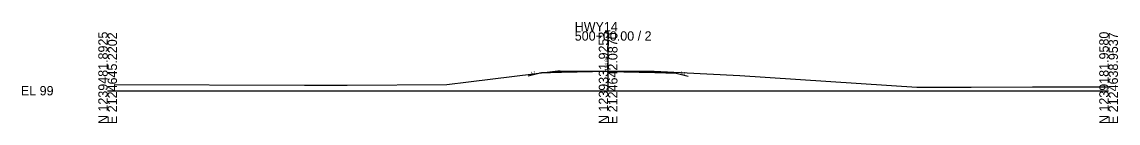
# Model space of a CAD drawing. Extents: x -26 to 303, y -10 to 11521.
# Drawn here: x -25.7 to 302.8, y 11490.3 to 11520.6 of the extents above; entities that cross this region are included whole.
import ezdxf

# ---------------------------------------------------------------- set-up
doc = ezdxf.new("R2010")
doc.units = 0
for name, color, linetype in [('XS_CELL', 7, 'Continuous'), ('XS_P_FINISHED_GRADE', 7, 'Continuous'), ('XS_P_SUBGRADE_GRANULAR', 7, 'Continuous'), ('XS_P_SUBGRADE_LEVELING', 7, 'Continuous'), ('XS_P_TX_FS_BS', 7, 'Continuous'), ('XS_X_GROUND', 7, 'Continuous'), ('XS_X_GROUND_TX', 7, 'Continuous')]:
    doc.layers.add(name, color=color, linetype=linetype)

msp = doc.modelspace()

# ---------------------------------------------------------------- linework, layer by layer
at = {"layer": 'XS_CELL'}
for p, q in [((150, 11500), (150, 11517.8)), ((0, 11500), (150, 11500)), ((150, 11500), (300, 11500))]:
    msp.add_line(p, q, dxfattribs=at)
at = {"layer": 'XS_P_FINISHED_GRADE'}
for p, q in [((130, 11505.38), (126, 11504.38)), ((136, 11505.62), (130, 11505.38)), ((150, 11505.9), (136, 11505.62)), ((150, 11505.9), (164, 11505.62)), ((164, 11505.62), (170, 11505.38)), ((170, 11505.38), (174, 11504.38))]:
    msp.add_line(p, q, dxfattribs=at)
at = {"layer": 'XS_P_SUBGRADE_GRANULAR'}
for p, q in [((136, 11505.5), (129.4, 11505.24)), ((164, 11505.5), (170.6, 11505.24))]:
    msp.add_line(p, q, dxfattribs=at)
at = {"layer": 'XS_P_SUBGRADE_LEVELING'}
for p, q in [((150, 11505.78), (136, 11505.5)), ((136, 11505.5), (136, 11505.62)), ((150, 11505.78), (164, 11505.5)), ((164, 11505.5), (164, 11505.62))]:
    msp.add_line(p, q, dxfattribs=at)
at = {"layer": 'XS_X_GROUND'}
for p, q in [((108.17, 11502.7), (134.88, 11505.93)), ((134.88, 11505.93), (135.62, 11505.93)), ((135.62, 11505.93), (150, 11505.9)), ((150, 11505.9), (163.75, 11505.88)), ((163.75, 11505.88), (189.49, 11504.58)), ((101.61, 11501.9), (108.17, 11502.7)), ((189.49, 11504.58), (242.57, 11501.02)), ((2, 11501.89), (59, 11501.66)), ((59, 11501.66), (65.13, 11501.64)), ((65.13, 11501.64), (71.74, 11501.69)), ((71.74, 11501.69), (101.61, 11501.9)), ((242.57, 11501.02), (258.84, 11501.07)), ((258.84, 11501.07), (277.15, 11501.13)), ((277.15, 11501.13), (300, 11501.18))]:
    msp.add_line(p, q, dxfattribs=at)

# ---------------------------------------------------------------- texts
at = {"layer": 'XS_CELL'}
for s, p in [('HWY14', (140, 11517.8)), ('500+00.00 / 2', (140, 11515)), ('EL 99', (-26, 11498.6))]:
    msp.add_text(s, height=2.8, dxfattribs=at).set_placement(p)
for s, p in [('N 1239481.8925', (0, 11490)), ('E 2124645.2202', (2.8, 11490)), ('N 1239331.9253', (150, 11490)), ('E 2124642.0870', (152.8, 11490)), ('N 1239181.9580', (300, 11490)), ('E 2124638.9537', (302.8, 11490))]:
    msp.add_text(s, height=2.8, rotation=90, dxfattribs=at).set_placement(p)
at = {"layer": 'XS_P_TX_FS_BS'}
for rotation, p in [(14.0362, (126.88, 11504.78)), (345.9638, (171.54, 11505.14))]:
    msp.add_text('4:1', height=0.8, rotation=rotation, dxfattribs=at).set_placement(p)
at = {"layer": 'XS_X_GROUND_TX'}
msp.add_text('104.90', height=1, rotation=90, dxfattribs=at).set_placement((150, 11506))

doc.saveas('drawing.dxf')
